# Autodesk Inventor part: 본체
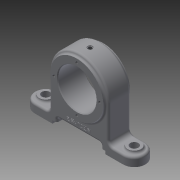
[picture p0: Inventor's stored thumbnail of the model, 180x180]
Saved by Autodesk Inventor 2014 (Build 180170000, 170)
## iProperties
Created: 2019-05
Part Number: 본체
Material: Generic
Document SubType Name: Modeling
Designer: kh
Density: 1 g/cm^3
Appearance: Default
Author: kh
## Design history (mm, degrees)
sketch "스케치1"
  geometry: L1 (-60, 0)-(60, 0); L2 (-60, -15)-(60, -15); L3 (60, 15)-(-60, 15); A1 r 15 centre (-60, 0) between (-60, 15) and (-60, -15); A2 r 15 centre (60, 0) between (60, -15) and (60, 15); 1 further point
  constraints: 8 end point, 4 point on circle, 4 tangent, 2 centre point, 1 horizontal, 1 midpoint, 1 parallel
  dimensions: "d0" = 60 distance of point (0, 0) L1.end; "d1" = 30 diameter of A2
extrude "돌출1" new body sketch "스케치1" distance "d2" = 12; taper "d3" = 0 deg
sketch "스케치2"
  geometry: C1 r 9 at (-60, 0); C2 r 9 at (60, 0); A1 r 15 centre (-60, 0) between (-60, 15) and (-60, -15) reference; A2 r 15 centre (60, 0) between (60, -15) and (60, 15) reference; 1 further point
  constraints: 2 centre point, 2 coincident
  dimensions: "d4" = 18 diameter of C1; "d5" = 18 diameter of C2
extrude "돌출2" join sketch "스케치2" distance "d6" = 3; taper "d7" = 0 deg
sketch "스케치3"
  geometry: L1 (-40, -15)-(40, -15); L2 (40, -15)-(40, 15); L3 (40, 15)-(-40, 15); L4 (-40, 15)-(-40, -15); L5 (-40, -15)-(40, 15); L6 (40, -15)-(-40, 15); L7 (60, 15)-(-60, 15) reference; 1 further point
  constraints: 12 end point, 2 midpoint, 2 parallel, 1 collinear, 1 horizontal, 1 perpendicular
  dimensions: "d8" = 80 distance between parallel lines of L2 L4
extrude "돌출3" join sketch "스케치3" distance "d9" = 88; taper "d10" = 0 deg
fillet "모깎기1" dims "d11" = 40
sketch "스케치4"
  geometry: C1 r 36 at (0, 60); A1 r 40 centre (0, 60) between (40, 60) and (-40, 60) reference; 1 further point
  constraints: 1 centre point, 1 coincident
  dimensions: "d12" = 72 diameter of C1
extrude "돌출4" join sketch "스케치4" stored distance "d13" = 36; taper "d14" = 0 deg
hole "구멍1" diameter "d17" = 52; stored, may be unused: countersink angle "d21" = 90 deg, drill point angle "d23" = 118 deg; dims "d15" = 10, "d16" = 10, "d18" = 6, "d19" = 4, "d20" = 2, "d22" = 8
hole "구멍2" diameter "d26" = 11; stored, may be unused: countersink angle "d30" = 90 deg, drill point angle "d32" = 118 deg; dims "d24" = 10, "d25" = 10, "d27" = 6, "d28" = 4, "d29" = 2, "d31" = 8
hole "구멍3" diameter "d35" = 11; stored, may be unused: countersink angle "d39" = 90 deg, drill point angle "d41" = 118 deg; dims "d33" = 10, "d34" = 10, "d36" = 6, "d37" = 4, "d38" = 2, "d40" = 8
sketch "스케치5"
  geometry: L1 (0, 0)-(0, 31); C1 r 26 at (0, 0) reference; 2 further points
  constraints: 2 end point, 1 coincident, 1 vertical
  dimensions: "d42" = 31 distance of L1.start L1.end
hole "구멍4" sketch "스케치5" at (0, 31) diameter "d43" = 3.459; stored, may be unused: countersink angle "d47" = 90 deg, drill point angle "d49" = 118 deg; dims "d44" = 6, "d45" = 4, "d46" = 2, "d48" = 8
node "작업 평면1"
sketch "스케치6"
  geometry: 2 further points
  constraints: 1 coincident
hole "구멍5" sketch "스케치6" diameter "d53" = 5.459; stored, may be unused: countersink angle "d57" = 90 deg, drill point angle "d59" = 118 deg; dims "d54" = 8, "d55" = 7, "d56" = 1, "d58" = 10
hole "구멍6" sketch "스케치6" diameter "d60" = 2; stored, may be unused: countersink angle "d64" = 90 deg, drill point angle "d66" = 0 deg; dims "d61" = 2, "d62" = 7, "d63" = 1, "d65" = 10
sketch "스케치10"
  geometry: L1 (0, 0)-(0, 34); 2 further points
  constraints: 2 end point, 1 point on line, 1 vertical, 1 vertical alignment, 1 other
hole "구멍7" sketch "스케치10" at (0, 26) diameter "d81" = 3; stored, may be unused: countersink angle "d85" = 90 deg, drill point angle "d87" = 118 deg; dims "d82" = 3, "d83" = 7, "d84" = 1, "d86" = 10
chamfer "모따기1" distance "d67" = 1; stored, may be unused: second distance "d68" = 2, angle "d69" = 45 deg
fillet "모깎기2" dims "d70" = 3, "d88" = 6
sketch "스케치7"
  geometry: L1 (-36, -15)-(36, -15); L2 (36, -15)-(36, 15); L3 (36, 15)-(-36, 15); L4 (-36, 15)-(-36, -15); L5 (-36, -15)-(36, 15); L6 (36, -15)-(-36, 15); L7 (-60, 15)-(60, 15) reference; 1 further point
  constraints: 12 end point, 2 midpoint, 2 parallel, 1 collinear, 1 horizontal, 1 perpendicular
  dimensions: "d71" = 72 distance between parallel lines of L2 L4
extrude "돌출5" cut sketch "스케치7" distance "d72" = 4; taper "d73" = 0 deg
sketch "스케치8"
  geometry: L1 (-30, -15)-(30, -15); L2 (30, -15)-(30, 15); L3 (30, 15)-(-30, 15); L4 (-30, 15)-(-30, -15); L5 (-30, -15)-(30, 15); L6 (30, -15)-(-30, 15); L7 (-36, 15)-(36, 15) reference; 1 further point
  constraints: 12 end point, 2 midpoint, 2 parallel, 1 collinear, 1 horizontal, 1 perpendicular
  dimensions: "d74" = 60 distance between parallel lines of L2 L4
extrude "돌출6" cut sketch "스케치8" distance "d75" = 6; taper "d76" = 0 deg
sketch "스케치9"
  geometry: L1 (-20.261, -40.598)-(20.261, -40.598); L2 (20.261, -40.598)-(20.261, -45.402); L3 (20.261, -45.402)-(-20.261, -45.402); L4 (-20.261, -45.402)-(-20.261, -40.598); L5 (-20.261, -43)-(20.261, -43); L6 (0, -40.598)-(0, -45.402); L7 (-30, -50)-(30, -50) reference; 1 further point
  constraints: 4 end point, 4 midpoint, 1 point on line, 2 other
  dimensions: "d77" = 7 distance between parallel lines of L7 L5
feature "엠보싱1" sketch "스케치9" dims "d0" = 60, "d1" = 30, "d8" = 80, "d78" = 0.5, "d79" = 0
fillet "모깎기3" dims "d80" = 3
node "솔리드1"
pattern_circular "원형 패턴1" dims angle "d51" = 360 deg
mirror "대칭1"
